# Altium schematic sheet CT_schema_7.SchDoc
size 308 x 210 mm
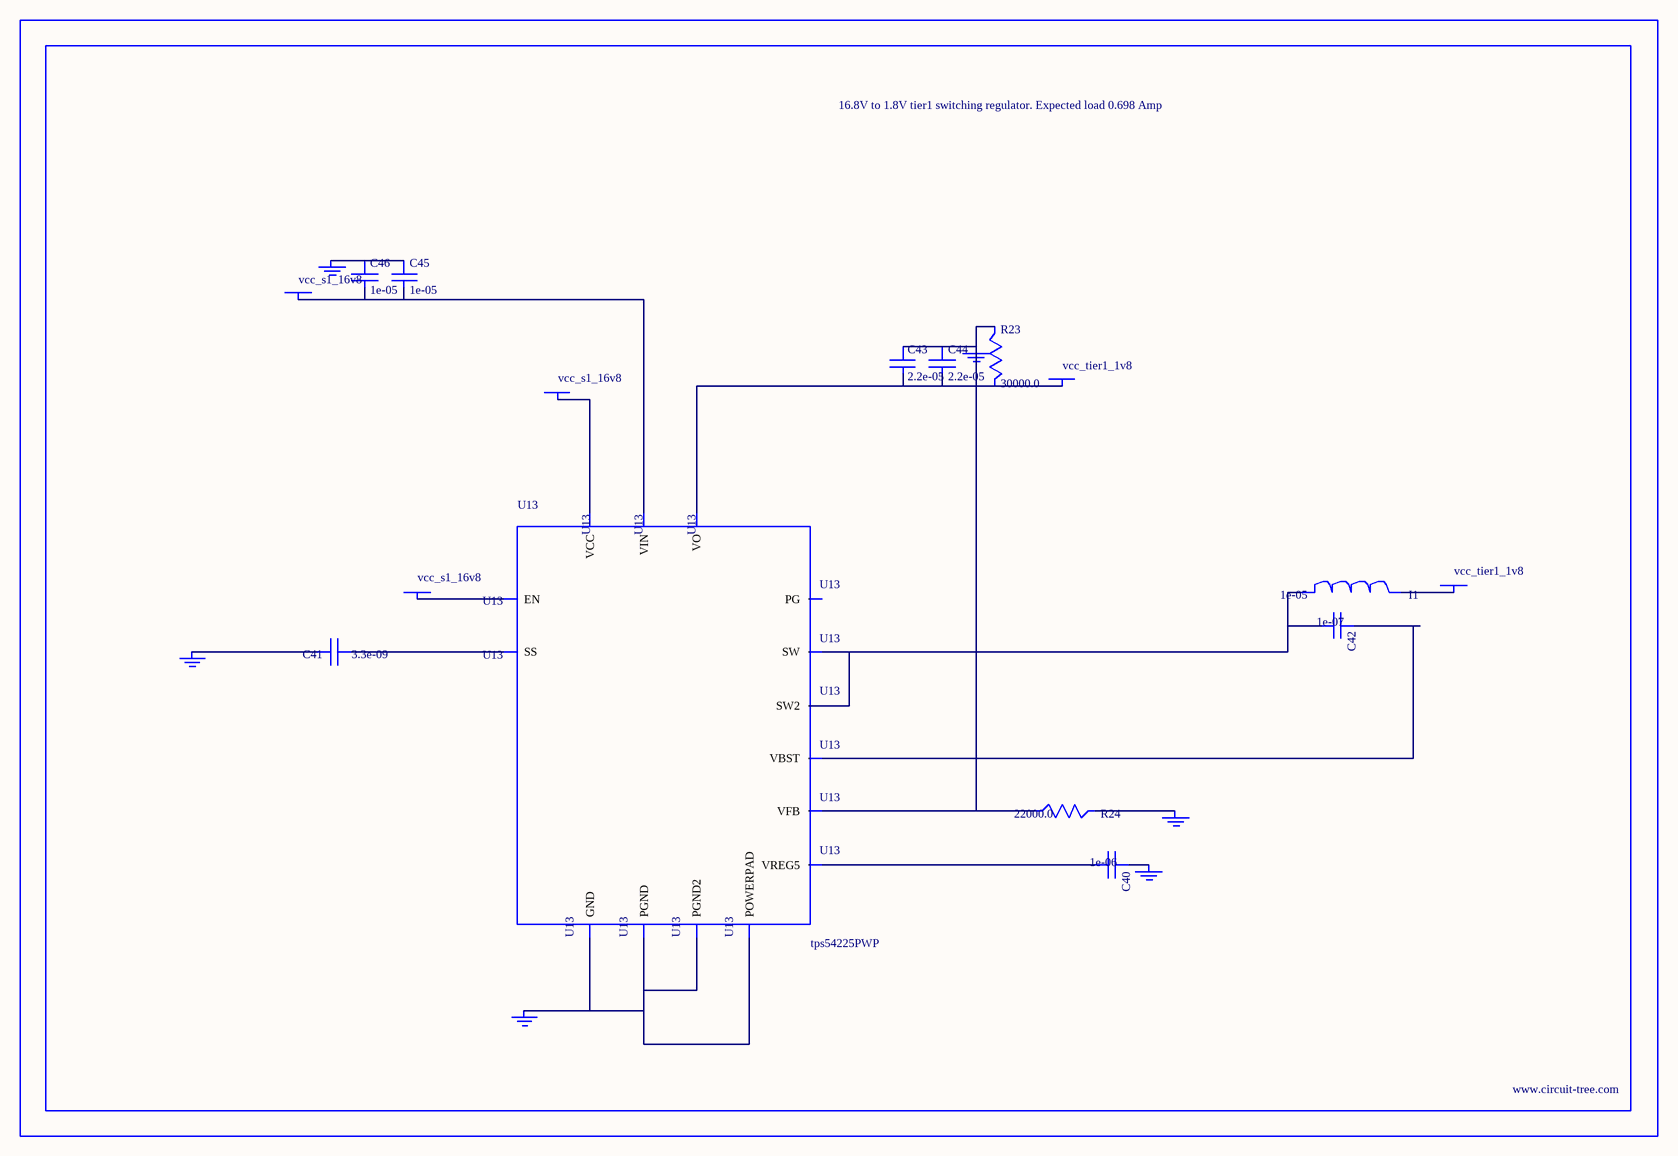
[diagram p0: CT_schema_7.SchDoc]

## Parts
BORDER6  (no value)
C40  1e-06  [C0603]
C41  3.3e-09  [C0402]
C42  1e-07  [C0402]
C43  2.2e-05  [C1210]
C44  2.2e-05  [C1210]
C45  1e-05  [C1210]
C46  1e-05  [C1210]
GND_INSTANCE_6_0  (no value)
GND_INSTANCE_6_1  (no value)
GND_INSTANCE_6_2  (no value)
GND_INSTANCE_6_3  (no value)
GND_INSTANCE_6_4  (no value)
GND_INSTANCE_6_5  (no value)
I1  1e-05  [IND_PM3316]
POWER_INSTANCE_6_0  vcc_tier1_1v8
POWER_INSTANCE_6_1  vcc_s1_16v8
POWER_INSTANCE_6_2  vcc_tier1_1v8
POWER_INSTANCE_6_3  vcc_s1_16v8
POWER_INSTANCE_6_4  vcc_s1_16v8
R23  30000.0  [R0603]
R24  22000.0  [R0603]
U13  tps54225PWP  [HTSSOP14]

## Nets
NetC40_1: C40.1 GND_INSTANCE_6_2.0(GND)
NetC40_2: C40.2 U13.3(VREG5)
NetC41_1: C41.1 U13.4(SS)
NetC41_2: C41.2 GND_INSTANCE_6_3.0(GND)
NetC42_1: C42.1 U13.12(VBST)
NetC42_2: C42.2 I1.1 U13.10(SW) U13.11(SW2)
NetC43_1: C43.1 C44.1 GND_INSTANCE_6_0.0(GND) R23.1 R24.1 U13.2(VFB)
NetC43_2: C43.2 C44.2 POWER_INSTANCE_6_0.0(PWR) R23.2 U13.1(VO)
NetC45_1: C45.1 C46.1 GND_INSTANCE_6_5.0(GND)
NetC45_2: C45.2 C46.2 POWER_INSTANCE_6_3.0(PWR) U13.13(VIN)
NetGND_INSTANCE_6_1_0: GND_INSTANCE_6_1.0(GND) R24.2
NetGND_INSTANCE_6_4_0: GND_INSTANCE_6_4.0(GND) U13.5(GND) U13.8(PGND) U13.9(PGND2) U13.15(POWERPAD)
NetI1_2: I1.2 POWER_INSTANCE_6_2.0(PWR)
NetPOWER_INSTANCE_6_1_0: POWER_INSTANCE_6_1.0(PWR) U13.7(EN)
NetPOWER_INSTANCE_6_4_0: POWER_INSTANCE_6_4.0(PWR) U13.14(VCC)

Not connected (* = marked no-connect by the designer): U13 6(PG)

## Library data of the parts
BORDER6 = BORDER_PAGE6
C40 = C0603C105K3RACTU
C41 = C0402C332K3RAC
C42 = C0402C104K3RACTU
C43 C44 = GRM32ER61E226ME15L
C45 C46 = C1210C106K5PACTU
GND_INSTANCE_6_0-GND_INSTANCE_6_5 = GND
I1 = PM3316-100M-RC
POWER_INSTANCE_6_0-POWER_INSTANCE_6_4 = PWR
R23 = RC0603JR-0730KL
R24 = RC0603JR-0722KL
